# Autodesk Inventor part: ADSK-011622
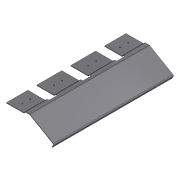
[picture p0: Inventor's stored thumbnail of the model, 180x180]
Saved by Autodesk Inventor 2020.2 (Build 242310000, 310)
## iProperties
Created: 2000-02
Part Number: ADSK-011622
Document SubType Name: Tôlerie
Designer: sspink
Material: 1.0312 DC05
Density: 1 g/cm^3
Sheet Metal Rule: Stahlblech 1.0312 - DC05 -   3.0 mm
Appearance: Metal-Steel(Polish)
Sheet Metal Width: 308,390 mm
Sheet Metal Length: 670,000 mm
Sheet Metal Area: 206621,511 mm^2
Mass: 566.381 g
Surface Area: 3860.78 cm^2
Volume: 566.381 cm^3
Flat Pattern Width: 30.839 cm
Flat Pattern Length: 67 cm
Flat Pattern Area: 2066.22 cm^2
Control State: 0
Checked Out: False
Master: False
Shininess: 57.0
Length Units: 11269
Angle Units: 11279
Time Units: 11290
Mass Units: 11283
Length Display Precision: 3
Angle Display Precision: 2
Compacted: True
G_L: 308,4x670 mm
Thickness: 3,000 mm
Dimensions: 98,3x670x266,1 mm
Mass: 0,566 kg
Semi finished: Stahlblech 1.0312 - DC05 -   3.0 mm
VLT_Material: 1.0312 DC05
Density: 8.03
Volumn: 572.0123911288352
Area: 3840.6777066757522
PropertySet Name: Model Information
Author: sspink
Revision Number: -
Title: ADSK-011622
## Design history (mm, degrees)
node "Konturlasche1"
  sketch "Skizze9"
    geometry: L1 (0, 0)-(97, 0); L2 (97, 0)-(106, 9); L3 (106, 9)-(131, 9); L4 (131, 9)-(268.265, -70.25); L5 (268.265, -70.25)-(257.265, -89.303)
    constraints: 10 end point, 1 horizontal, 1 parallel, 1 perpendicular
    dimensions: "d62" = 97 distance of L1.start L1.end; "d63" = 25 distance of L2.end L3.end; "d64" = 9 distance between parallel lines of L1 L3; "d65" = 45 deg angle of L1 L2; "d66" = 30 deg angle of L3 L4; "d67" = 158.5 distance of L3.end L4.end; "d68" = 22 distance of L4.end L5.end
sketch "Skizze10"
  geometry: L1 (0, 0)-(0, 670) reference; L2 (0, 360)-(120, 360); L3 (120, 360)-(120, 310); L4 (120, 310)-(0, 310); L5 (0, 310)-(0, 360); 3 further points
  constraints: 8 end point, 2 midpoint, 2 parallel, 1 coincident, 1 horizontal, 1 perpendicular, 1 point on line
  dimensions: "d80" = 120 distance of L3.end L4.end; "d81" = 50 distance between parallel lines of L4 L2
feature "Ausklinkung3" sketch "Skizze10" dims "d82" = 3 (= Thickness), "d83" = 0
feature "Eckenrundung2" dims "d84" = 6
pattern_linear "Rechteckige Anordnung5" dims "d87" = 190
sketch "Skizze11"
  geometry: L1 (50, -276)-(50, -321); L2 (50, 92.5)-(50, 47.5); L3 (50, 271)-(50, 226); L4 (50, -97.5)-(50, -142.5); L5 (0, 190)-(0, 310) reference; L6 (0, 0)-(0, 140) reference; L7 (0, -190)-(0, -50) reference; L8 (0, -360)-(0, -240) reference; L9 (95.757, -240)-(0, -240) reference; L10 (0, 190)-(95.757, 190) reference; 17 further points
  constraints: 8 coincident, 8 end point, 8 midpoint, 4 vertical, 3 collinear, 2 horizontal alignment
  dimensions: "d88" = 45 distance of L1.start L1.end; "d89" = 45 distance of L2.start L2.end; "d90" = 45 distance of L3.start L3.end; "d91" = 45 distance of L4.start L4.end; "d92" = 50 distance between parallel lines of L5 L3; "d100" = 36 distance from line of L9 point (50, -276); "d101" = 36 distance from line of L10 point (50, 226) (= d100)
hole "Bohrung2" sketch "Skizze11" at (50, -276), (50, -321), (50, 47.5), (50, 92.5), (50, 226), (50, 271), (50, -142.5), (50, -97.5) diameter "d93" = 6.6; stored, may be unused: countersink angle "d97" = 90 deg, drill point angle "d99" = 118 deg; dims "d94" = 6, "d95" = 14.5, "d96" = 2, "d98" = 3 (= Thickness)
node "Volumenkörper2"
node "Corps solides"
node "Corps surfaciques"
feature "Grobblech6" dims "d69" = 3 (= Thickness), "d70" = 3 (= BendReliefWidth), "d71" = 1.5 (= BendReliefDepth), "d72" = 6 (= MinimumRemnant), "d73" = 3 (= TransitionRadius), "d74" = 670, "d75" = 3 (= BendRadius), "d76" = 3, "d77" = 12 (= CornerReliefSize), "d78" = 3 (= TailleJeu), "d79" = 3 (= TailleRayonJacobi), "SeamGap" = 0.00508
feature "Biegung5" dims "d69" = 3 (= Thickness), "d70" = 3 (= BendReliefWidth), "d71" = 1.5 (= BendReliefDepth), "d72" = 6 (= MinimumRemnant), "d73" = 3 (= TransitionRadius), "d75" = 3 (= BendRadius), "d76" = 3, "SeamGap" = 0.00508
feature "Ecke1" dims "d76" = 3, "d77" = 12 (= CornerReliefSize), "d78" = 3 (= TailleJeu), "d79" = 3 (= TailleRayonJacobi)
feature "Definition1"
other parameters: "Thickness" = 3 (derived), "BendRadius" = 3 (= Thickness), "BendReliefWidth" = 3 (= Thickness), "BendReliefDepth" = 1.5 (= 0.5 x Thickness), "CornerReliefSize" = 12 (= 4 x Thickness), "MinimumRemnant" = 6 (= 2 x Thickness), "d2" = 3 (= BendRadius), "TransitionRadius" = 3 (= BendRadius), "TailleRayonJacobi" = 3 (= BendRadius), "TailleJeu" = 3 (= Thickness), "BendRadius" = 3, "BendReliefDepth" = 1.5, "BendReliefWidth" = 3, "CornerReliefSize" = 12, "MinimumRemnant" = 6, "TailleJeu" = 3, "TailleRayonJacobi" = 3, "Thickness" = 3, "TransitionRadius" = 3
